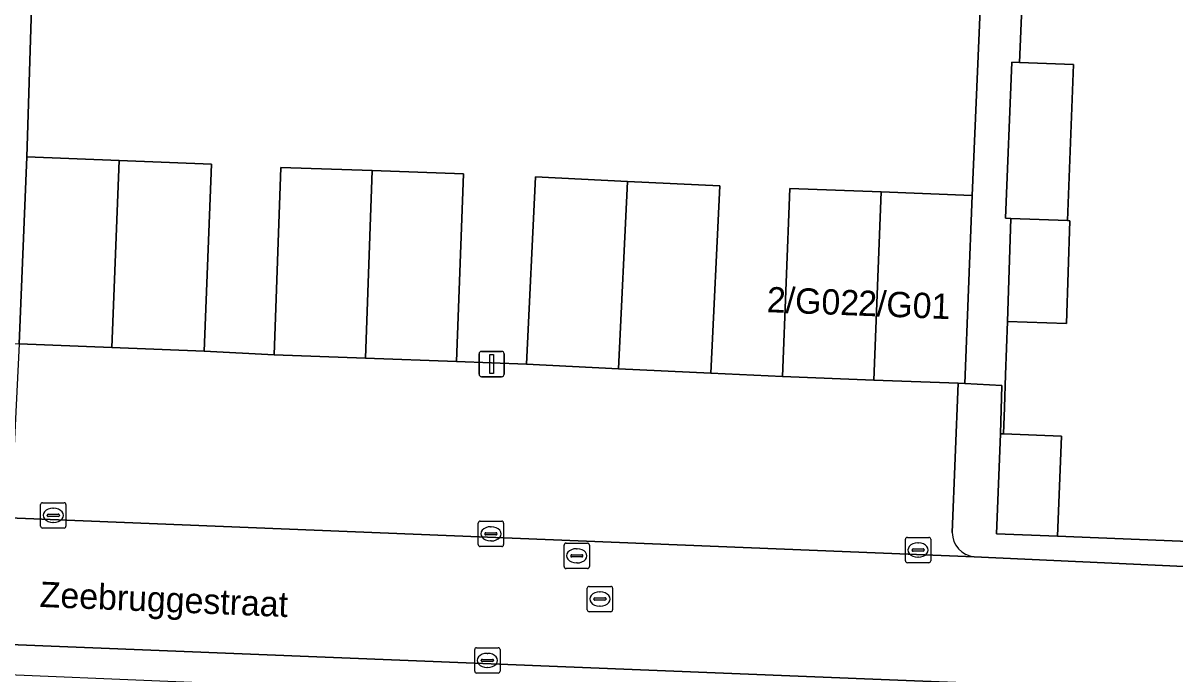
# Model space of a CAD drawing. Extents: x 160732 to 162107, y 387428 to 388479.
# Drawn here: x 161190.39 to 161235.89, y 387617.33 to 387643.04 of the extents above; entities that cross this region are included whole.
import ezdxf

# ---------------------------------------------------------------- set-up
doc = ezdxf.new("R2010")
doc.units = 0
for name, color, linetype in [('IMGEO_Erf', 7, 'Continuous'), ('IMGEO_Kolk', 7, 'Continuous'), ('IMGEO_Lichtmast', 7, 'Continuous'), ('IMGEO_Muur', 7, 'Continuous'), ('IMGEO_Openbare_ruimte_label', 7, 'Continuous'), ('IMGEO_Pand', 7, 'Continuous'), ('IMGEO_Pand_nummerreeks', 7, 'Continuous'), ('IMGEO_Parkeervlak_open', 7, 'Continuous'), ('IMGEO_Rijbaan_lokaal_open', 7, 'Continuous'), ('IMGEO_Rioolput', 7, 'Continuous'), ('IMGEO_Voetpad_open', 7, 'Continuous')]:
    doc.layers.add(name, color=color, linetype=linetype)

msp = doc.modelspace()

# ---------------------------------------------------------------- linework, layer by layer
at = {"layer": 'IMGEO_Erf'}
for points in [[(161250.028, 387666.535), (161230.667, 387667.288), (161230.39, 387660.156), (161232.775, 387660.079), (161232.651, 387656.239), (161230.266, 387656.316), (161230.059, 387650.723), (161232.395, 387650.649), (161232.298, 387647.581), (161232.172, 387643.582), (161229.836, 387643.655), (161229.751, 387641.477), (161231.879, 387641.395), (161231.64, 387635.231), (161231.733, 387635.227), (161231.605, 387631.171), (161229.269, 387631.245), (161229.187, 387629.136), (161229.148, 387627.846), (161229.108, 387626.805), (161231.401, 387626.716), (161231.248, 387622.767), (161239.991, 387622.408)], [(161190.916, 387649.969), (161190.532, 387637.753), (161194.182, 387637.608), (161197.833, 387637.463), (161197.539, 387630.07), (161200.305, 387629.928), (161200.572, 387637.336), (161204.175, 387637.206), (161207.778, 387637.077), (161207.511, 387629.668), (161210.27, 387629.558), (161210.625, 387636.957), (161214.265, 387636.782), (161217.904, 387636.608), (161217.548, 387629.208), (161220.386, 387629.073), (161220.673, 387636.507), (161224.276, 387636.368), (161227.878, 387636.228), (161228.578, 387652.458)]]:
    msp.add_lwpolyline(points, dxfattribs=at)
at = {"layer": 'IMGEO_Kolk'}
for p, q in [((161191.08, 387623.165), (161191.08, 387624.017)), ((161191.155, 387624.091), (161192.007, 387624.091)), ((161191.568, 387623.871), (161191.593, 387623.871)), ((161192.081, 387624.017), (161192.081, 387623.165)), ((161191.339, 387623.585), (161191.339, 387623.597)), ((161191.777, 387623.548), (161191.379, 387623.548)), ((161191.382, 387623.634), (161191.78, 387623.634)), ((161191.591, 387623.311), (161191.566, 387623.311)), ((161191.823, 387623.597), (161191.823, 387623.585)), ((161208.441, 387623.361), (161209.293, 387623.361)), ((161192.007, 387623.091), (161191.155, 387623.091)), ((161208.366, 387622.435), (161208.366, 387623.287)), ((161208.625, 387622.855), (161208.625, 387622.867)), ((161208.668, 387622.904), (161209.066, 387622.904)), ((161208.854, 387623.141), (161208.879, 387623.141)), ((161209.109, 387622.867), (161209.109, 387622.855)), ((161209.367, 387623.287), (161209.367, 387622.435)), ((161209.063, 387622.818), (161208.665, 387622.818)), ((161208.877, 387622.581), (161208.852, 387622.581)), ((161225.241, 387621.795), (161225.241, 387622.647)), ((161225.316, 387622.721), (161226.168, 387622.721)), ((161225.729, 387622.501), (161225.754, 387622.501)), ((161226.242, 387622.647), (161226.242, 387621.795)), ((161209.293, 387622.361), (161208.441, 387622.361)), ((161225.5, 387622.215), (161225.5, 387622.227)), ((161225.938, 387622.178), (161225.54, 387622.178)), ((161225.543, 387622.264), (161225.941, 387622.264)), ((161225.984, 387622.227), (161225.984, 387622.215)), ((161226.168, 387621.721), (161225.316, 387621.721)), ((161225.752, 387621.941), (161225.727, 387621.941)), ((161208.301, 387618.36), (161209.153, 387618.36)), ((161208.226, 387617.434), (161208.226, 387618.286)), ((161208.485, 387617.854), (161208.485, 387617.866)), ((161208.528, 387617.903), (161208.926, 387617.903)), ((161208.714, 387618.14), (161208.739, 387618.14)), ((161208.969, 387617.866), (161208.969, 387617.854)), ((161209.227, 387618.286), (161209.227, 387617.434)), ((161208.923, 387617.817), (161208.525, 387617.817)), ((161208.737, 387617.58), (161208.712, 387617.58)), ((161209.153, 387617.36), (161208.301, 387617.36))]:
    msp.add_line(p, q, dxfattribs=at)
for points in [[(161191.08, 387623.165), (161191.08, 387624.017)], [(161191.155, 387624.091), (161192.007, 387624.091)], [(161192.081, 387624.017), (161192.081, 387623.165)], [(161208.441, 387623.361), (161209.293, 387623.361)], [(161192.007, 387623.091), (161191.155, 387623.091)], [(161208.366, 387622.435), (161208.366, 387623.287)], [(161209.367, 387623.287), (161209.367, 387622.435)], [(161225.241, 387621.795), (161225.241, 387622.647)], [(161225.316, 387622.721), (161226.168, 387622.721)], [(161226.242, 387622.647), (161226.242, 387621.795)], [(161209.293, 387622.361), (161208.441, 387622.361)], [(161226.168, 387621.721), (161225.316, 387621.721)], [(161208.301, 387618.36), (161209.153, 387618.36)], [(161208.226, 387617.434), (161208.226, 387618.286)], [(161209.227, 387618.286), (161209.227, 387617.434)], [(161209.153, 387617.36), (161208.301, 387617.36)]]:
    msp.add_lwpolyline(points, dxfattribs=at)
for centre, radius, start, end in [((161191.157, 387624.015), 0.0765, 91.552, 178.448), ((161191.157, 387624.015), 0.0765, 91.552, 178.448), ((161192.005, 387624.015), 0.0765, 1.552, 88.448), ((161192.005, 387624.015), 0.0765, 1.552, 88.448), ((161191.379, 387623.594), 0.0403, 85.8775, 175.7526), ((161191.376, 387623.584), 0.0366, 178.938, 274.7102), ((161191.78, 387623.591), 0.043, 264.8664, 352.4533), ((161191.784, 387623.596), 0.0386, 1.7309, 96.639), ((161208.443, 387623.285), 0.0765, 91.552, 178.448), ((161208.443, 387623.285), 0.0765, 91.552, 178.448), ((161209.291, 387623.285), 0.0765, 1.552, 88.448), ((161209.291, 387623.285), 0.0765, 1.552, 88.448), ((161191.157, 387623.167), 0.0765, 181.552, 268.448), ((161191.157, 387623.167), 0.0765, 181.552, 268.448), ((161192.005, 387623.167), 0.0765, 271.552, 358.448), ((161192.005, 387623.167), 0.0765, 271.552, 358.448), ((161208.665, 387622.864), 0.0403, 85.8775, 175.7526), ((161208.662, 387622.854), 0.0366, 178.938, 274.7102), ((161209.066, 387622.861), 0.043, 264.8664, 352.4533), ((161209.07, 387622.866), 0.0386, 1.7309, 96.639), ((161208.443, 387622.437), 0.0765, 181.552, 268.448), ((161208.443, 387622.437), 0.0765, 181.552, 268.448), ((161209.291, 387622.437), 0.0765, 271.552, 358.448), ((161209.291, 387622.437), 0.0765, 271.552, 358.448), ((161225.318, 387622.645), 0.0765, 91.552, 178.448), ((161225.318, 387622.645), 0.0765, 91.552, 178.448), ((161226.166, 387622.645), 0.0765, 1.552, 88.448), ((161226.166, 387622.645), 0.0765, 1.552, 88.448), ((161225.54, 387622.224), 0.0403, 85.8775, 175.7526), ((161225.537, 387622.214), 0.0366, 178.938, 274.7102), ((161225.941, 387622.221), 0.043, 264.8664, 352.4533), ((161225.945, 387622.226), 0.0386, 1.7309, 96.639), ((161225.318, 387621.797), 0.0765, 181.552, 268.448), ((161225.318, 387621.797), 0.0765, 181.552, 268.448), ((161226.166, 387621.797), 0.0765, 271.552, 358.448), ((161226.166, 387621.797), 0.0765, 271.552, 358.448), ((161208.303, 387618.284), 0.0765, 91.552, 178.448), ((161208.303, 387618.284), 0.0765, 91.552, 178.448), ((161209.151, 387618.284), 0.0765, 1.552, 88.448), ((161209.151, 387618.284), 0.0765, 1.552, 88.448), ((161208.525, 387617.863), 0.0403, 85.8775, 175.7526), ((161208.522, 387617.853), 0.0366, 178.938, 274.7102), ((161208.926, 387617.86), 0.043, 264.8664, 352.4533), ((161208.93, 387617.865), 0.0386, 1.7309, 96.639), ((161208.303, 387617.436), 0.0765, 181.552, 268.448), ((161208.303, 387617.436), 0.0765, 181.552, 268.448), ((161209.151, 387617.436), 0.0765, 271.552, 358.448), ((161209.151, 387617.436), 0.0765, 271.552, 358.448)]:
    msp.add_arc(centre, radius, start, end, dxfattribs=at)
for centre, major_axis, ratio, start_param, end_param in [((161191.567, 387623.591), (-0.387, 0.002), 0.722429, 4.712389, 7.853982), ((161191.592, 387623.591), (-0.39, 0.002), 0.717154, 1.570796, 4.712389), ((161208.853, 387622.861), (-0.387, 0.002), 0.722429, 4.712389, 7.853982), ((161208.878, 387622.861), (-0.39, 0.002), 0.717154, 1.570796, 4.712389), ((161225.728, 387622.221), (-0.387, 0.002), 0.722429, 4.712389, 7.853982), ((161225.753, 387622.221), (-0.39, 0.002), 0.717154, 1.570796, 4.712389), ((161208.713, 387617.86), (-0.387, 0.002), 0.722429, 4.712389, 7.853982), ((161208.738, 387617.86), (-0.39, 0.002), 0.717154, 1.570796, 4.712389)]:
    msp.add_ellipse(centre, major_axis=major_axis, ratio=ratio, start_param=start_param, end_param=end_param, dxfattribs=at)
at = {"layer": 'IMGEO_Lichtmast'}
for p, q in [((161208.398, 387629.168), (161208.398, 387629.968)), ((161208.398, 387629.968), (161208.398, 387629.168)), ((161208.498, 387630.068), (161209.288, 387630.068)), ((161209.288, 387630.068), (161208.498, 387630.068)), ((161209.388, 387629.968), (161209.388, 387629.168)), ((161209.388, 387629.168), (161209.388, 387629.968)), ((161209.288, 387629.068), (161208.498, 387629.068)), ((161208.498, 387629.068), (161209.288, 387629.068))]:
    msp.add_line(p, q, dxfattribs=at)
msp.add_lwpolyline([(161208.818, 387629.943), (161208.968, 387629.943), (161208.968, 387629.193), (161208.818, 387629.193), (161208.818, 387629.943)], dxfattribs=at)
for centre, start, end in [((161208.498, 387629.968), 90, 180), ((161208.498, 387629.968), 90, 180), ((161209.288, 387629.968), 0, 90), ((161209.288, 387629.968), 360, 90), ((161208.498, 387629.168), 180, 270), ((161208.498, 387629.168), 180, 270), ((161209.288, 387629.168), 270, 0), ((161209.288, 387629.168), 270, 0)]:
    msp.add_arc(centre, 0.1, start, end, dxfattribs=at)
at = {"layer": 'IMGEO_Muur'}
msp.add_lwpolyline([(161231.248, 387622.767), (161239.991, 387622.408)], dxfattribs=at)
at = {"layer": 'IMGEO_Pand'}
for points in [[(161229.751, 387641.477), (161229.437, 387641.489), (161229.198, 387635.325), (161229.397, 387635.317), (161231.64, 387635.231), (161231.879, 387641.395)], [(161193.889, 387630.215), (161194.182, 387637.608), (161190.532, 387637.753), (161190.239, 387630.36)], [(161197.539, 387630.07), (161197.833, 387637.463), (161194.182, 387637.608), (161193.889, 387630.215)], [(161203.908, 387629.798), (161204.175, 387637.206), (161200.572, 387637.336), (161200.305, 387629.928)], [(161207.511, 387629.668), (161207.778, 387637.077), (161204.175, 387637.206), (161203.908, 387629.798)], [(161213.909, 387629.383), (161214.265, 387636.782), (161210.625, 387636.957), (161210.27, 387629.558)], [(161217.548, 387629.208), (161217.904, 387636.608), (161214.265, 387636.782), (161213.909, 387629.383)], [(161224.276, 387636.368), (161220.673, 387636.507), (161220.386, 387629.073), (161223.988, 387628.934)], [(161227.591, 387628.795), (161227.878, 387636.228), (161224.276, 387636.368), (161223.988, 387628.934), (161227.324, 387628.806)], [(161231.733, 387635.227), (161231.64, 387635.231), (161229.397, 387635.317), (161229.269, 387631.245), (161231.605, 387631.171)], [(161231.401, 387626.716), (161229.108, 387626.805), (161228.993, 387626.809), (161228.839, 387622.86), (161231.248, 387622.767)]]:
    msp.add_lwpolyline(points, close=True, dxfattribs=at)
at = {"layer": 'IMGEO_Parkeervlak_open'}
for points in [[(161227.087, 387622.912), (161227.324, 387628.806), (161223.988, 387628.934), (161220.386, 387629.073), (161217.548, 387629.208), (161213.909, 387629.383), (161210.27, 387629.558), (161207.511, 387629.668), (161203.908, 387629.798), (161200.305, 387629.928), (161197.539, 387630.07), (161193.889, 387630.215), (161190.239, 387630.36), (161189.945, 387624.458)], [(161189.162, 387623.521), (161227.956, 387621.958)]]:
    msp.add_lwpolyline(points, dxfattribs=at)
msp.add_arc((161228.054, 387622.92), 0.967, 180.4818, 264.1791, dxfattribs=at)
at = {"layer": 'IMGEO_Rijbaan_lokaal_open'}
msp.add_lwpolyline([(161253.433, 387620.949), (161237.391, 387621.523), (161227.956, 387621.958), (161189.162, 387623.521), (161160.07, 387624.724), (161159.879, 387619.683), (161189.142, 387618.507), (161189.538, 387618.499), (161234.447, 387616.696), (161235.056, 387616.672), (161251.616, 387615.972), (161253.289, 387615.895)], close=True, dxfattribs=at)
at = {"layer": 'IMGEO_Rioolput'}
for p, q in [((161211.758, 387621.566), (161211.758, 387622.418)), ((161211.833, 387622.492), (161212.685, 387622.492)), ((161212.759, 387622.418), (161212.759, 387621.566)), ((161212.017, 387621.986), (161212.017, 387621.998)), ((161212.455, 387621.949), (161212.057, 387621.949)), ((161212.06, 387622.035), (161212.458, 387622.035)), ((161212.246, 387622.272), (161212.271, 387622.272)), ((161212.501, 387621.998), (161212.501, 387621.986)), ((161212.685, 387621.492), (161211.833, 387621.492)), ((161212.269, 387621.712), (161212.244, 387621.712)), ((161212.672, 387619.859), (161212.672, 387620.711)), ((161212.747, 387620.785), (161213.599, 387620.785)), ((161213.673, 387620.711), (161213.673, 387619.859)), ((161212.931, 387620.279), (161212.931, 387620.291)), ((161213.369, 387620.242), (161212.971, 387620.242)), ((161212.974, 387620.328), (161213.372, 387620.328)), ((161213.16, 387620.565), (161213.185, 387620.565)), ((161213.415, 387620.291), (161213.415, 387620.279)), ((161213.599, 387619.785), (161212.747, 387619.785)), ((161213.183, 387620.005), (161213.158, 387620.005))]:
    msp.add_line(p, q, dxfattribs=at)
for points in [[(161211.758, 387621.566), (161211.758, 387622.418)], [(161211.833, 387622.492), (161212.685, 387622.492)], [(161212.759, 387622.418), (161212.759, 387621.566)], [(161212.685, 387621.492), (161211.833, 387621.492)], [(161212.672, 387619.859), (161212.672, 387620.711)], [(161212.747, 387620.785), (161213.599, 387620.785)], [(161213.673, 387620.711), (161213.673, 387619.859)], [(161213.599, 387619.785), (161212.747, 387619.785)]]:
    msp.add_lwpolyline(points, dxfattribs=at)
for centre, radius, start, end in [((161211.835, 387622.416), 0.0765, 91.552, 178.448), ((161211.835, 387622.416), 0.0765, 91.552, 178.448), ((161212.683, 387622.416), 0.0765, 1.552, 88.448), ((161212.683, 387622.416), 0.0765, 1.552, 88.448), ((161212.057, 387621.995), 0.0403, 85.8775, 175.7526), ((161212.054, 387621.985), 0.0366, 178.938, 274.7102), ((161212.458, 387621.992), 0.043, 264.8664, 352.4533), ((161212.462, 387621.997), 0.0386, 1.7309, 96.639), ((161211.835, 387621.568), 0.0765, 181.552, 268.448), ((161211.835, 387621.568), 0.0765, 181.552, 268.448), ((161212.683, 387621.568), 0.0765, 271.552, 358.448), ((161212.683, 387621.568), 0.0765, 271.552, 358.448), ((161212.749, 387620.709), 0.0765, 91.552, 178.448), ((161212.749, 387620.709), 0.0765, 91.552, 178.448), ((161213.597, 387620.709), 0.0765, 1.552, 88.448), ((161213.597, 387620.709), 0.0765, 1.552, 88.448), ((161212.971, 387620.288), 0.0403, 85.8775, 175.7526), ((161212.968, 387620.278), 0.0366, 178.938, 274.7102), ((161213.372, 387620.285), 0.043, 264.8664, 352.4533), ((161213.376, 387620.29), 0.0386, 1.7309, 96.639), ((161212.749, 387619.861), 0.0765, 181.552, 268.448), ((161212.749, 387619.861), 0.0765, 181.552, 268.448), ((161213.597, 387619.861), 0.0765, 271.552, 358.448), ((161213.597, 387619.861), 0.0765, 271.552, 358.448)]:
    msp.add_arc(centre, radius, start, end, dxfattribs=at)
for centre, major_axis, ratio, start_param, end_param in [((161212.245, 387621.992), (-0.387, 0.002), 0.722429, 4.712389, 7.853982), ((161212.27, 387621.992), (-0.39, 0.002), 0.717154, 1.570796, 4.712389), ((161213.159, 387620.285), (-0.387, 0.002), 0.722429, 4.712389, 7.853982), ((161213.184, 387620.285), (-0.39, 0.002), 0.717154, 1.570796, 4.712389)]:
    msp.add_ellipse(centre, major_axis=major_axis, ratio=ratio, start_param=start_param, end_param=end_param, dxfattribs=at)
at = {"layer": 'IMGEO_Voetpad_open'}
for points in [[(161190.916, 387649.969), (161191.08, 387653.992), (161191.193, 387656.764), (161191.398, 387661.759), (161191.672, 387668.805), (161190.137, 387668.865), (161189.863, 387661.822), (161189.749, 387658.042), (161189.591, 387658.047), (161189.489, 387658.05), (161189.309, 387653.088), (161189.175, 387649.377), (161189.041, 387645.666), (161188.951, 387643.195), (161188.861, 387640.723), (161188.727, 387637.012), (161188.593, 387633.302), (161188.489, 387630.449), (161190.239, 387630.36), (161190.532, 387637.753)], [(161229.963, 387647.672), (161230.059, 387650.723), (161230.266, 387656.316), (161230.39, 387660.156), (161230.667, 387667.288), (161229.173, 387667.346), (161228.896, 387660.226), (161228.692, 387655.231), (161228.578, 387652.458), (161227.878, 387636.228), (161227.591, 387628.795), (161229.044, 387628.723), (161228.993, 387626.809), (161229.108, 387626.805), (161229.148, 387627.846), (161229.187, 387629.136), (161229.269, 387631.245), (161229.397, 387635.317), (161229.198, 387635.325), (161229.437, 387641.489), (161229.751, 387641.477), (161229.836, 387643.655)], [(161189.538, 387618.499), (161189.465, 387617.313), (161208.407, 387616.534), (161234.394, 387615.505), (161234.447, 387616.696)]]:
    msp.add_lwpolyline(points, close=True, dxfattribs=at)
for points in [[(161254.025, 387621.801), (161247.834, 387622.086), (161239.991, 387622.408), (161231.248, 387622.767), (161228.839, 387622.86), (161228.993, 387626.809), (161229.044, 387628.723), (161227.591, 387628.795), (161227.324, 387628.806), (161227.087, 387622.912)], [(161227.956, 387621.958), (161237.391, 387621.523), (161253.433, 387620.949), (161255.509, 387620.866)]]:
    msp.add_lwpolyline(points, dxfattribs=at)
msp.add_arc((161228.054, 387622.92), 0.967, 180.4818, 264.1791, dxfattribs=at)

# ---------------------------------------------------------------- texts
at = {"layer": 'IMGEO_Openbare_ruimte_label'}
msp.add_text('Zeebruggestraat', height=1, rotation=357.6498, dxfattribs=at).set_placement((161191.03, 387619.975))
at = {"layer": 'IMGEO_Pand_nummerreeks'}
for s, rotation, p in [('2/G02', 357.7939, (161219.752, 387631.619)), ('2/G01', 357.7868, (161223.355, 387631.481))]:
    msp.add_text(s, height=1, rotation=rotation, dxfattribs=at).set_placement(p)

doc.saveas('drawing.dxf')
